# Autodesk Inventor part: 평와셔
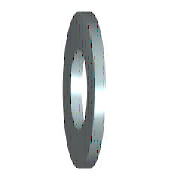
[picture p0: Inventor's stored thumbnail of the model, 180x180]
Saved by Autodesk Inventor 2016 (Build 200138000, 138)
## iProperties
IsCustomPart: 1
Created: 2012-02
Part Number: 평와셔
Material: 강철
Description: 평면 와셔 - 초대형 시리즈 - 제품 등급 C
Document SubType Name: Modeling
Standard: ISO 7094
Designer: mduedu
Standard Revision: Second edition 2000-06-01
Standards Organization: ISO
Language: ko-KR
Size Designation: ST 5 - 100 HV
Categories: <MemberInstance><Categories><Category DisplayName="조임쇠" InternalName="e4da775c-781d-43d5-af7c-5136215cf5a6" Mnemonic="FSTN"><Category DisplayName="와셔" InternalN
Density: 7.85 g/cm^3
Appearance: 강철
Author: mduedu
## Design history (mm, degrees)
sketch "스케치"
  geometry: C1 r 9 at (0, 0); C2 r 2.75 at (0, 0); 1 further point
  constraints: 2 centre point, 2 coincident
  dimensions: "d0" = 5.5 diameter of C2 (= SD1); "d1" = 18 diameter of C1 (= SD2)
extrude "본체" new body sketch "스케치" distance "d2" = 2 (= SD); taper "d3" = 0 deg
workaxis "Work Axis1"
workplane "Work Plane1"
body "Solid1"
other parameters: "SD1" = 5.5 [user parameter; used in 1 equation term], "SD2" = 18 [user parameter; used in 1 equation term], "SD" = 2 [user parameter; used in 1 equation term], "d4" = 0, "d5" = 0, "d6" = 0, "d7" = 0, "NND" = 5 [user parameter]
